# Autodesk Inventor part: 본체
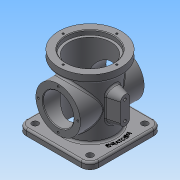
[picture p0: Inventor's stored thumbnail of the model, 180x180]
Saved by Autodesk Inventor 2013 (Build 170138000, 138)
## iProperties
Created: 2021-03
Part Number: 본체
Material: 일반
Document SubType Name: Modeling
Designer: Administrator
Density: 1 g/cm^3
Author: Administrator
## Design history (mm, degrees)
sketch "스케치1"
  geometry: L1 (57, -57)-(-57, -57); L2 (-57, -57)-(-57, 57); L3 (-57, 57)-(57, 57); L4 (57, 57)-(57, -57); L5 (57, -57)-(-57, 57); L6 (-57, -57)-(57, 57); C1 r 38 at (0, 0); 1 further point
  constraints: 12 end point, 3 midpoint, 2 parallel, 2 perpendicular, 1 centre point, 1 horizontal
  dimensions: "d0" = 114 distance of L2.end L3.end; "d4" = 76 diameter of C1
extrude "돌출1" new body sketch "스케치1" distance "d2" = 10; taper "d3" = 0 deg
extrude "돌출2" join sketch "스케치1" distance "d5" = 98; taper "d6" = 0 deg
sketch "스케치2"
  geometry: C1 r 49 at (0, 0); 1 further point
  constraints: 1 centre point, 1 coincident
  dimensions: "d7" = 98 diameter of C1
extrude "돌출3" join sketch "스케치2" distance "d9" = 13; taper "d10" = 0 deg
sketch "스케치3"
  geometry: C1 r 35 at (0, 54); 1 further point
  constraints: 1 centre point, 1 vertical alignment
  dimensions: "d20" = 70 diameter of C1; "d22" = 54 distance of point (0, 0) C1.centre
extrude "돌출4" join sketch "스케치3" stored distance "d24" = 100; taper "d25" = 0 deg
hole "구멍2" diameter "d28" = 66; stored, may be unused: countersink angle "d32" = 90 deg, drill point angle "d34" = 0 deg; dims "d26" = 10, "d27" = 10, "d29" = 6, "d30" = 74, "d31" = 7, "d33" = 111
hole "구멍3" diameter "d37" = 48; stored, may be unused: countersink angle "d41" = 90 deg, drill point angle "d43" = 0 deg; dims "d35" = 10, "d36" = 10, "d38" = 6, "d39" = 74, "d40" = 7, "d42" = 111
sketch "스케치4"
  geometry: 2 further points
  constraints: 1 vertical alignment
  dimensions: "d44" = 42 distance of point (0, 42) point (0, 0)
hole "구멍4" sketch "스케치4" at (0, 42) diameter "d45" = 3.242; stored, may be unused: countersink angle "d49" = 90 deg, drill point angle "d51" = 118 deg; dims "d46" = 6, "d47" = 74, "d48" = 7, "d50" = 8
sketch "스케치5"
  geometry: L1 (54, 57)-(54, -57) reference; C1 r 24 at (0, 0) reference; 3 further points
  constraints: 1 horizontal alignment, 1 midpoint
  dimensions: "d55" = 31 distance of point (-31, 0) C1.centre
hole "구멍5" sketch "스케치5" at (-31, 0) diameter "d56" = 3.242; stored, may be unused: countersink angle "d60" = 90 deg, drill point angle "d62" = 118 deg; dims "d57" = 6, "d58" = 74, "d59" = 7, "d61" = 8
node "작업 평면1"
sketch "스케치6"
  geometry: L1 (7, 41)-(7, 70); L2 (-7, 70)-(-7, 41); L3 (50, 19)-(50, 89) reference; L4 (57, 0)-(-57, 0) reference; A1 r 7 centre (0, 70) between (7, 70) and (-7, 70); A2 r 7 centre (0, 41) between (-7, 41) and (7, 41); 3 further points
  constraints: 4 end point, 4 point on circle, 4 tangent, 2 centre point, 2 midpoint, 2 vertical alignment, 1 parallel, 1 vertical
  dimensions: "d67" = 43 dimension on A2 A1; "d69" = 7 radius of A1; "d114" = 13 vertical distance of point (50, 54) A2.centre
extrude "돌출5" join sketch "스케치6" stored distance "d70" = 100; taper "d71" = 15 deg
fillet "모깎기1" dims "d72" = 14
hole "구멍6" diameter "d75" = 10; stored, may be unused: countersink angle "d79" = 90 deg, drill point angle "d81" = 0 deg; dims "d73" = 10, "d74" = 10, "d76" = 6, "d77" = 74, "d78" = 7, "d80" = 8
fillet "모깎기2" dims "d88" = 3
chamfer "모따기1" distance "d89" = 1; stored, may be unused: second distance "d90" = 2, angle "d91" = 45 deg
hole "구멍7" diameter "d94" = 4.134; stored, may be unused: countersink angle "d98" = 90 deg, drill point angle "d100" = 118 deg; dims "d92" = 10, "d93" = 10, "d95" = 8, "d96" = 74, "d97" = 7, "d99" = 10
hole "구멍8" diameter "d103" = 4.134; stored, may be unused: countersink angle "d107" = 90 deg, drill point angle "d109" = 118 deg; dims "d101" = 10, "d102" = 10, "d104" = 8, "d105" = 74, "d106" = 7, "d108" = 10
sketch "스케치7"
  geometry: C1 r 50 at (0, 0); 1 further point
  constraints: 1 centre point, 1 coincident, 1 other
  dimensions: "d110" = 100 diameter of C1
feature "엠보싱1" sketch "스케치7" dims "d0" = 114, "d4" = 76, "d112" = 0.5, "d113" = 0
node "솔리드1"
pattern_circular "원형 패턴1" dims angle "d53" = 360 deg
pattern_circular "원형 패턴2" dims angle "d64" = 360 deg
mirror "대칭1"
pattern_linear "직사각형 패턴1" dims "d84" = 86, "d87" = 86
other parameters: "d66" = 55
